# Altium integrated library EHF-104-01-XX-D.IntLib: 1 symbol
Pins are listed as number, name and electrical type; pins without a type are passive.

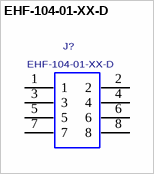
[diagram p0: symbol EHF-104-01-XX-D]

## EHF-104-01-XX-D
designator J?
0.050"EJECTOR HEADER ASSEMBLY, 8 PINS.; MANUFACTURER: SAMTEC
footprint EHF-104-01-XX-D
pins: 1, 2, 3, 4, 5, 6, 7, 8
